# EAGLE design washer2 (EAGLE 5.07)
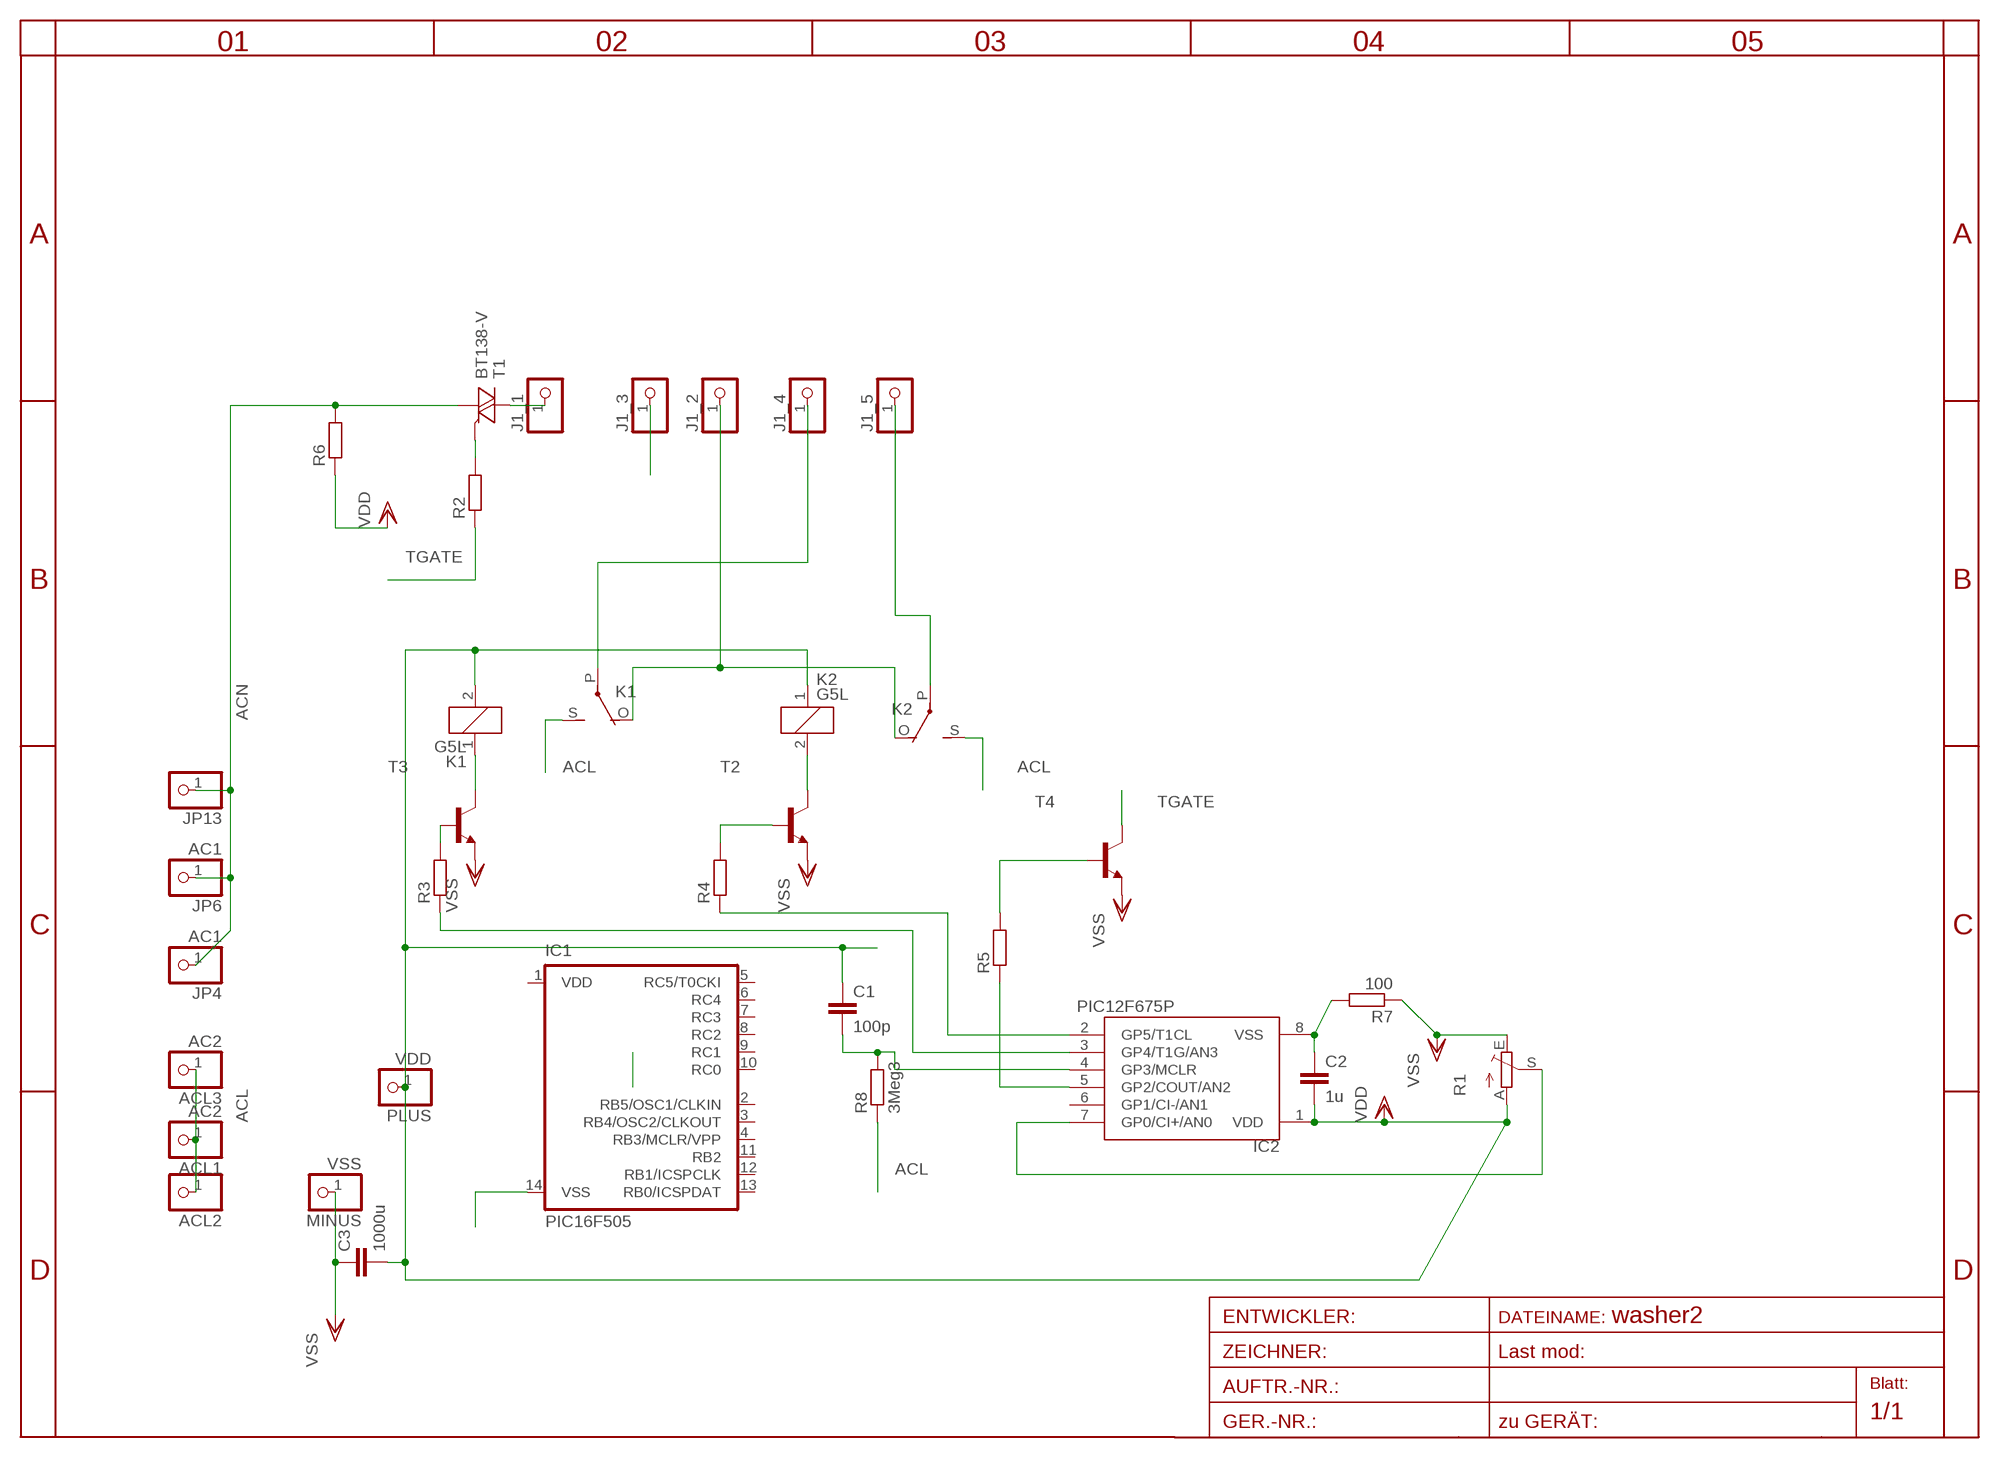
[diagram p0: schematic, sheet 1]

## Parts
ACL1  AC2  PINHD-1X11MM0  [1X1MM0]
ACL2  PINHD-1X11MM0  [1X1MM0]
ACL3  AC2  PINHD-1X11MM0  [1X1MM0]
C1  100p  C-EU025-024X044  [C025-024X044]
C2  1u  C-EU025-024X044  [C025-024X044]
C3  1000u  C-EU025-040X050  [C025-040X050]
IC1  PIC16F505  [DIL14]
IC2  PIC12F675P  [DIL8]
J1_1  PINHD-1X11MM0  [1X1MM0]
J1_2  PINHD-1X11MM0  [1X1MM0]
J1_3  PINHD-1X11MM0  [1X1MM0]
J1_4  PINHD-1X11MM0  [1X1MM0]
J1_5  PINHD-1X11MM0  [1X1MM0]
JP4  AC1  PINHD-1X11MM0  [1X1MM0]
JP6  AC1  PINHD-1X11MM0  [1X1MM0]
JP13  PINHD-1X11MM6  [1X1MM8]
K1  G5L  [G5LE]
K2  G5L  [G5LE]
MINUS  VSS  PINHD-1X11MM0  [1X1MM0]
PLUS  VDD  PINHD-1X11MM0  [1X1MM0]
R1  TRIM_EU-RAND160  [RANDL]
R2  R-EU_0204/7  [0204/7]
R3  R-EU_0204/7  [0204/7]
R4  R-EU_0204/7  [0204/7]
R5  R-EU_0207/15  [0207/15]
R6  R-EU_0204/7  [0204/7]
R7  100  R-EU_0204/7  [0204/7]
R8  3Meg3  R-EU_0204/7  [0204/7]
T1  BT138-V  [TO220BV]
T2  BC337-16-NPN-TO92-EBC  [TO92-EBC]
T3  BC337-16-NPN-TO92-EBC  [TO92-EBC]
T4  BC337-16-NPN-TO92-EBC  [TO92-EBC]

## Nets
ACL: ACL1.1 ACL2.1 ACL3.1 K1.S(2:S) K2.S(2:S) R8.1
ACN: JP4.1 JP6.1 JP13.1 R6.2 T1.T1(A1)
N$1: C2.1 IC2.8(VSS) R7.2
N$2: K1.1 T3.C
N$3: R5.2 T4.B
N$4: R2.2 T1.G
N$5: R4.2 T2.B
N$6: IC2.7(GP0/CI+/AN0) R1.S
N$7: K2.2 T2.C
N$8: IC1.14(VSS)
N$9: IC2.2(GP5/T1CL) R4.1
N$12: IC2.3(GP4/T1G/AN3) R3.1
N$13: R3.2 T3.B
N$14: IC2.5(GP2/COUT/AN2) R5.1
N$16: C1.2 IC2.4(GP3/MCLR) R8.2
ROTA: J1_4.1 K1.P(2:P)
ROTB: J1_5.1 K2.P(2:P)
STATB: J1_2.1 K1.O(2:O) K2.O(2:O)
STATC: J1_3.1
STATOR: J1_1.1 T1.T2(A2)
TGATE: R2.1 T4.C
VDD: C1.1 C2.2 C3.2 IC2.1(VDD) K1.2 K2.1 PLUS.1 R1.A R6.1
VSS: C3.1 MINUS.1 R1.E R7.1 T2.E T3.E T4.E
Unconnected: IC1.2(RB5/OSC1/CLKIN) IC1.3(RB4/OSC2/CLKOUT) IC1.4(RB3/MCLR/VPP) IC1.5(RC5/T0CKI) IC1.6(RC4) IC1.7(RC3) IC1.8(RC2) IC1.9(RC1) IC1.10(RC0) IC1.11(RB2) IC1.12(RB1/ICSPCLK) IC1.13(RB0/ICSPDAT) IC2.6(GP1/CI-/AN1)

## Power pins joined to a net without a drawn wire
VDD: IC1.1(VDD)

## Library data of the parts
ACL1-ACL3 J1_1-J1_5 JP4 JP6 JP13 MINUS PLUS = pinhead:PINHD-1X1: PIN HEADER
C1-C3 = rcl:C-EU: CAPACITOR, European symbol
IC1 = microchip-5:PIC16F505: MICROCONTROLLER 1k Program Flash memory 72 bytes SRAM 12 I/O One 8-bit timer (TMR0) Precision 4 MHz internal oscillator
IC2 = microchip-5:PIC12F6*: uPC nW 1k Program Flash memory 2x Timer Comparator 10b A/D converter/ 4xIN
K1 K2 = relay:G5L: RELAY 1 x switch, 10 A/120 V AC, 8 A/30 V ADC, Omron
R1 = pot:TRIM_EU-: POTENTIOMETER
R2-R8 = rcl:R-EU_: RESISTOR, European symbol
T1 = triac:BT138: TRIAC Source: http://www.semiconductors.philips.com BT138_SERIES_2.pdf
T2-T4 = transistor:*-NPN-: NPN Transistror BF959 corrected 2008.03.06

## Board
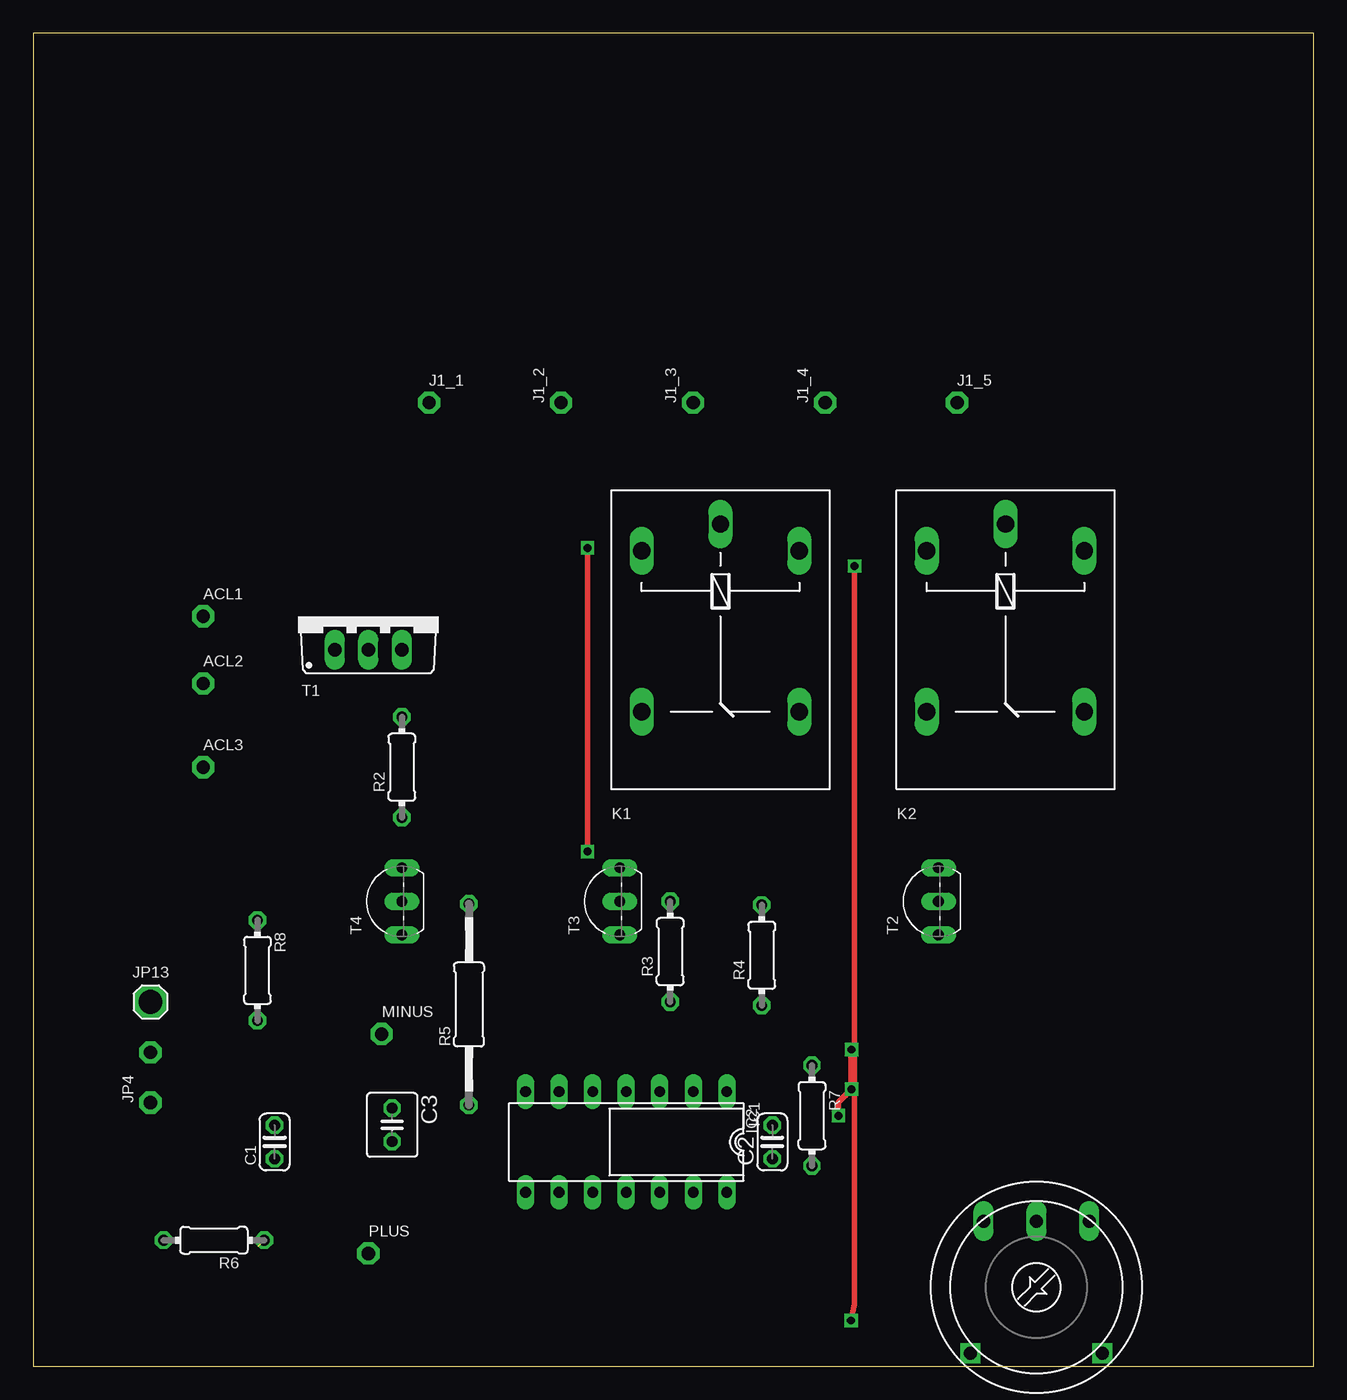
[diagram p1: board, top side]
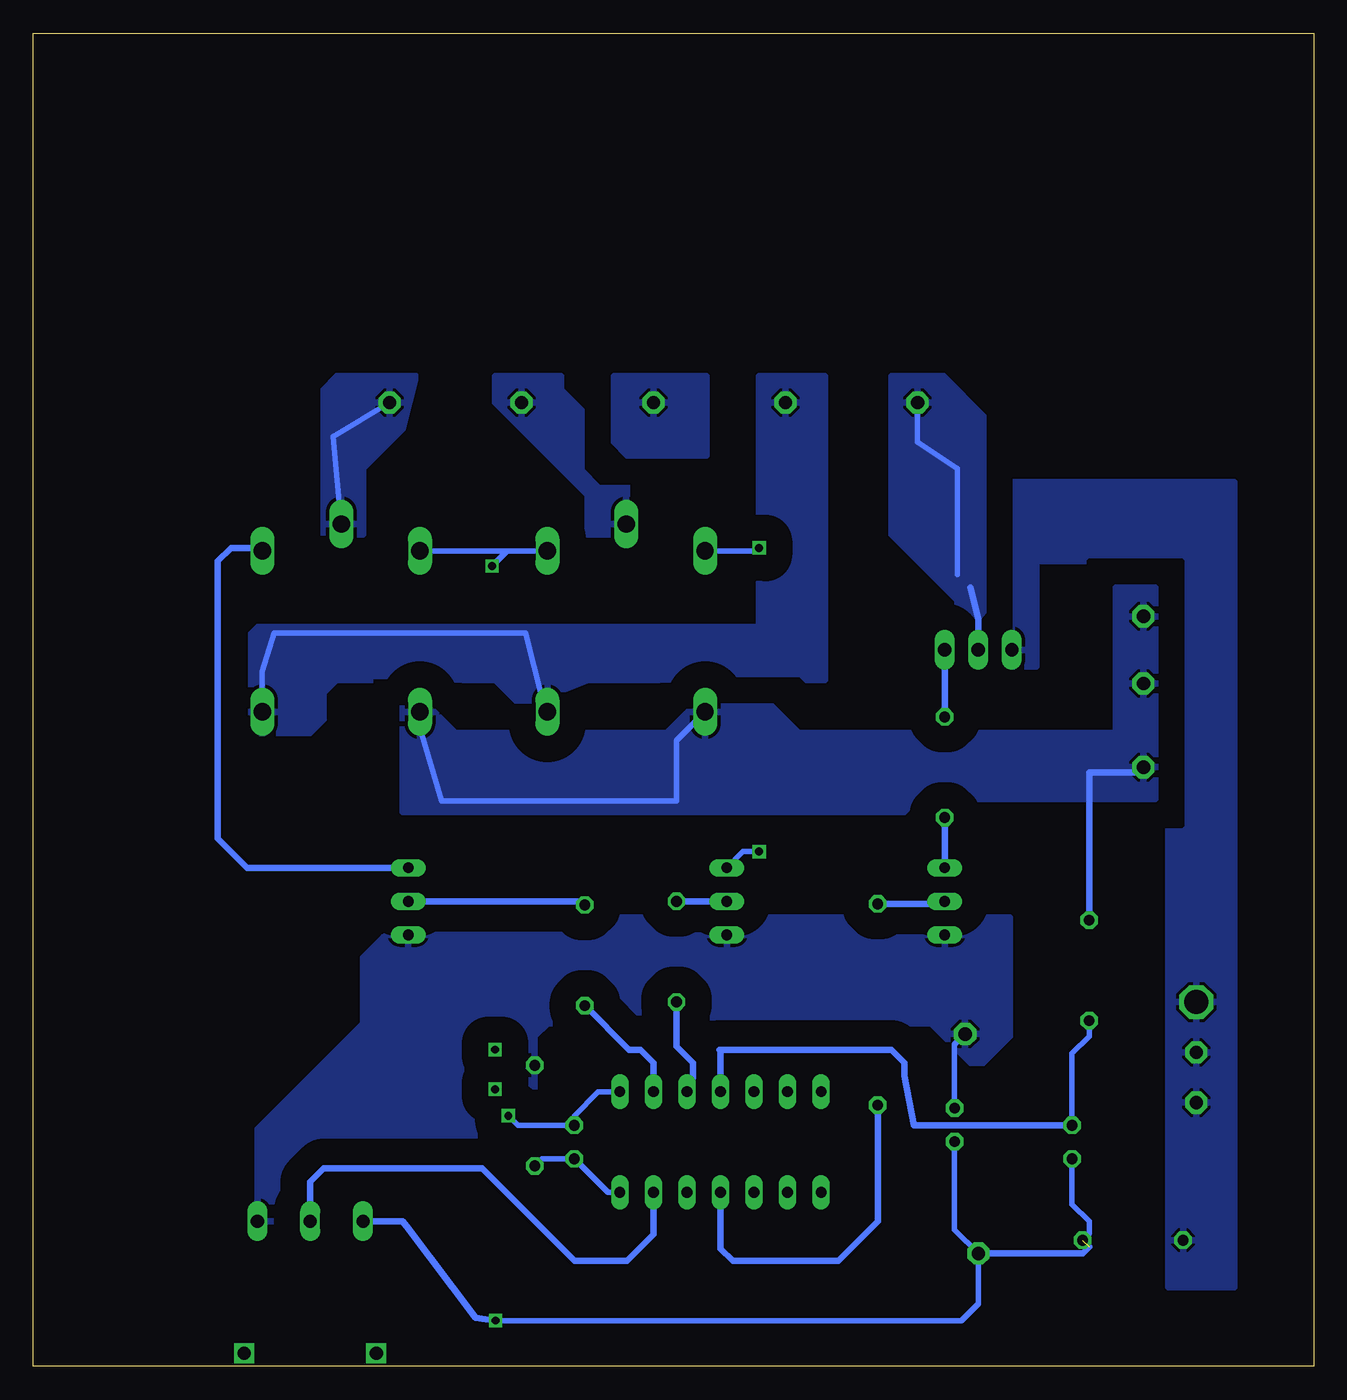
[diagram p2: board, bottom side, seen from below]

Size 97 x 101 mm. Coordinates in mm from the lower left corner, seen from the top.
Outline: 0,0 97,0 97,101 0,101 0,0
Copper layers (1*16): Top 0.035mm / dielectric 1.5mm / Bottom 0.035mm
Design rules "default *": minimum track width 10mil, minimum drill 20mil, track to track 8mil, track to pad 8mil, pad to pad 8mil, via to via 8mil, smd to smd 8mil, copper to edge 40mil, drill to drill 8mil, minimum pad ring 10mil, minimum via ring 8mil, stop-mask expansion 4mil, vias tented up to drill 0mil, thermal gap 10mil

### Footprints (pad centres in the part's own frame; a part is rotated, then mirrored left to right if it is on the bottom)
1X1MM0 = drill 1 pad 1.676 octagon: 1 0,0
C025-024X044 = drill 0.813 octagon: 1 -1.27,0; 2 1.27,0
C025-040X050 = drill 0.813 octagon: 1 -1.27,0; 2 1.27,0
DIL14 = drill 0.813 long: 1 -7.62,-3.81; 2 -5.08,-3.81; 3 -2.54,-3.81; 4 0,-3.81; 5 2.54,-3.81; 6 5.08,-3.81; 7 7.62,-3.81; 8 7.62,3.81; 9 5.08,3.81; 10 2.54,3.81; 11 0,3.81; 12 -2.54,3.81; 13 -5.08,3.81; 14 -7.62,3.81
DIL8 = drill 0.8 long: 1 -3.81,-3.81; 2 -1.27,-3.81; 3 1.27,-3.81; 4 3.81,-3.81; 5 3.81,3.81; 6 1.27,3.81; 7 -1.27,3.81; 8 -3.81,3.81
1X1MM8 = drill 1.8 pad 2.54 octagon: 1 0,0
G5LE = drill 1.321 long: 1 -7.493,-5.969; 2 -7.493,5.969; O 4.699,5.969; P -9.525,0; S 4.699,-5.969
RANDL = drill 1 long: A -4,5; E 4,5; S 0,5 | drill 1 square: P$1 -5,-5; P$2 5,-5
0204/7 = drill 0.813 octagon: 1 -3.81,0; 2 3.81,0
0207/15 = drill 0.813 octagon: 1 -7.62,0; 2 7.62,0
TO220BV = drill 1.016 long: G 2.54,-2.54; T1 -2.54,-2.54; T2 0,-2.54
TO92-EBC = drill 0.813 long: B 0,-1.27; C 2.54,-1.27; E -2.54,-1.27

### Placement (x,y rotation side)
ACL1  12.89,56.82 0 top
ACL2  12.89,51.74 0 top
ACL3  12.89,45.39 0 top
C1  18.3,17 90 top
C2  56,17 90 top
C3  27.2,18.3 270 top
IC1  44.93,17 180 top
IC2  48.74,17 180 top
J1_1  30,73 0 top
J1_2  40,73 90 top
J1_3  50,73 90 top
J1_4  60,73 90 top
J1_5  70,73 0 top
JP4  8.89,19.99 90 top
JP6  8.89,23.8 0 top
JP13  8.89,27.61 0 top
K1  52.07,54.28 270 top
K2  73.66,54.28 270 top
MINUS  26.4,25.18 0 top
PLUS  25.4,8.56 0 top
R1  76,6 0 top
R2  27.94,45.39 90 top
R3  48.26,31.42 90 top
R4  55.2,31.15 90 top
R5  33.02,27.42 90 top
R6  13.7,9.56 180 top
R7  59,19 270 top
R8  17,30 270 top
T1  25.4,56.82 0 top
T2  67.31,35.23 90 top
T3  43.18,35.23 90 top
T4  26.67,35.23 90 top

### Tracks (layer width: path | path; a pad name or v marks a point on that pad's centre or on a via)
ACL
  Bottom 0.406: K2.S 67.69,48.31 66.04,42.85 48.26,42.85 48.26,47.42 K1.S
  Bottom 0.5: R8.1 17,45 13.28,45 ACL3.1
  pour Bottom (isolate 2): 12,59 15,59 15,58 15,48 39,48 41,50 47,50 49,48 65,48 67,50 69,50 69,42 31,42 30,43 12,43
ACN
  pour Bottom (isolate 2, rank 2): 21,53 25,53 25,67 6,67 6,66 6,6 11,6 11,7 11,61 21,61 21,59
N$1
  Bottom 0.406: IC2.8 53.46,13.19 C2.1 58.46,15.73 R7.2
N$2  (via drill 0.6)
  Top 0.406: v42,39 v42,62
  Bottom 0.406: K1.1 42.23,61.77 v42,62 | v42,39 43.22,39 T3.C
N$3
  Bottom 0.5: R5.2 28.13,35.04 T4.B
N$4
  Bottom 0.5: R2.2 T1.G
N$5
  Bottom 0.5: T2.B 55.47,35.23 R4.2
N$6
  Bottom 0.5: R1.S 76,14 75,15 63,15 56,8 52,8 50,10 IC2.7
N$7
  Bottom 0.5: T2.C 80.77,37.77 83,40 83,61 82,62 79.86,62 K2.2
N$9
  Bottom 0.5: IC2.2 50.01,23.01 51,24 51.86,24 R4.1
N$12
  Bottom 0.5: R3.1 48.26,24.26 47,23 47,21.91 IC2.3
N$13
  Bottom 0.5: T3.B R3.2
N$14
  Bottom 0.5: IC2.5 44.93,8.93 44,8 36,8 33,11 33,19.78 R5.1
N$16
  Bottom 0.406: C1.2 18.3,23.7 17,25 R8.2
  Bottom 0.5: IC2.4 44.93,23.93 45,24 32,24 31,23 31,22 30.27,18.27 C1.2
ROTA
  pour Bottom (isolate 2, rank 2): 57,75 62,75 62,73 59,70 55,66 55,63 52,63 52,69 55,72 57,74
ROTB
  Bottom 0.406: J1_5.1 74.28,70.42 K2.P
  pour Bottom (isolate 2, rank 2): 68,75 74,75 75,74 75,63 72,63 72,68 69,71
STATB
  Bottom 0.406: K2.O 79.63,52.63 78.74,55.55 59.69,55.55 58.42,50.47 58.42,49.96 K1.O
  pour Bottom (isolate 2, rank 3): 37,75 42,75 42,56 80,56 81,55 81,48 76,48 75,49 75,51 74,52 62,52 60,50 55,52 37,52
STATC
  pour Bottom (isolate 2): 48,75 53,75 53,70 52,69 46,69 46,75
STATOR
  Bottom 0.406: J1_1.1 30,70 27,68 27,60
  Bottom 0.5: T1.T2 25.4,56.6 26,59
  pour Bottom (isolate 2): 28,75 32,75 32,63 27,58 27,54 25,54 25,72
TGATE
  Bottom 0.5: T4.C R2.1
VDD  (via drill 0.6)  (1 unrouted)
  Top 0.406: v62.23,60.63 62.23,21 62.23,4.75 v61.96,3.48 | v61,19 61,20 v62,21
  Top 0.5: v62,24 v62,21 62,21.23 62.23,21
  Bottom 0.406: K2.1 K1.2 61.09,61.77 v62.23,60.63 | v61.96,3.48 26.67,3.48 25.4,4.75 PLUS.1 27.2,10.36 C3.2 | IC2.1 54.19,20.81 56,19 C2.2 60.27,18.27 v61,19 | C1.1 18.3,12.3 17,11 17,10.07 R6.1
  Bottom 0.5: R1.A 69,11 68.7,10.6 63.48,3.7 v61.96,3.48 | PLUS.1 17.49,8.56 17,9.05
VSS
  Bottom 0.406: C3.1 27.2,24.38 MINUS.1
  pour Bottom (isolate 2, rank 2): 23,34 69,34 72,31 72,26 80,18 80,11 81,10 79,10 78,11 78,12 73,17 58,17 53,12 51,14 51,15 54,18 57,18 59,20 59,25 58,26 29,26 26,23 25,23 23,25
